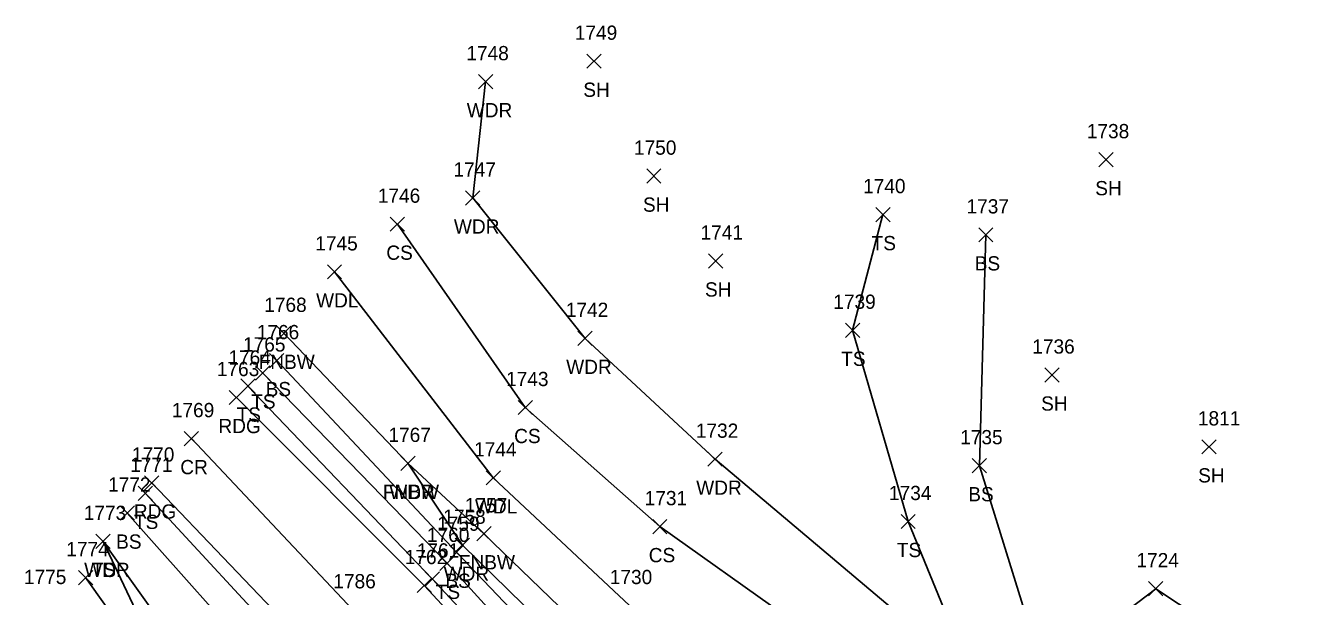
# Model space of a CAD drawing. Extents: x 1469310 to 1475157, y 493997 to 498873.
# Drawn here: x 1469330.9 to 1469508.8, y 498792.5 to 498872.6 of the extents above; entities that cross this region are included whole.
import ezdxf

# ---------------------------------------------------------------- set-up
doc = ezdxf.new("R2010")
doc.units = 0
for name, color, linetype in [('L_A', 7, 'Continuous'), ('L_I', 7, 'Continuous'), ('L_TIC', 7, 'Continuous'), ('LAWA', 7, 'Continuous'), ('LELB', 7, 'Continuous'), ('LFNC', 7, 'Continuous'), ('P_A', 7, 'Continuous'), ('P_I', 7, 'Continuous'), ('P_TIC', 7, 'Continuous'), ('PEU', 7, 'Continuous'), ('PRC', 7, 'Continuous')]:
    doc.layers.add(name, color=color, linetype=linetype)

msp = doc.modelspace()

# ---------------------------------------------------------------- linework, layer by layer
at = {"layer": 'L_TIC'}
for points in [[(1469409.64, 498866.62), (1469411.64, 498868.62)], [(1469411.64, 498866.62), (1469409.64, 498868.62)], [(1469394.42, 498863.75), (1469396.42, 498865.75)], [(1469396.42, 498863.75), (1469394.42, 498865.75)], [(1469481.45, 498852.81), (1469483.45, 498854.81)], [(1469483.45, 498852.81), (1469481.45, 498854.81)], [(1469418.02, 498850.5), (1469420.02, 498852.5)], [(1469420.02, 498850.5), (1469418.02, 498852.5)], [(1469392.62, 498847.43), (1469394.62, 498849.43)], [(1469394.62, 498847.43), (1469392.62, 498849.43)], [(1469450.16, 498845.1), (1469452.16, 498847.1)], [(1469452.16, 498845.1), (1469450.16, 498847.1)], [(1469382.05, 498843.76), (1469384.05, 498845.76)], [(1469384.05, 498843.76), (1469382.05, 498845.76)], [(1469464.59, 498842.26), (1469466.59, 498844.26)], [(1469466.59, 498842.26), (1469464.59, 498844.26)], [(1469373.23, 498837.07), (1469375.23, 498839.07)], [(1469375.23, 498837.07), (1469373.23, 498839.07)], [(1469426.71, 498838.6), (1469428.71, 498840.6)], [(1469428.71, 498838.6), (1469426.71, 498840.6)], [(1469366.12, 498828.45), (1469368.12, 498830.45)], [(1469368.12, 498828.45), (1469366.12, 498830.45)], [(1469445.9, 498828.88), (1469447.9, 498830.88)], [(1469447.9, 498828.88), (1469445.9, 498830.88)], [(1469408.37, 498827.74), (1469410.37, 498829.74)], [(1469410.37, 498827.74), (1469408.37, 498829.74)], [(1469365.13, 498824.62), (1469367.13, 498826.62)], [(1469367.13, 498824.62), (1469365.13, 498826.62)], [(1469363.14, 498822.89), (1469365.14, 498824.89)], [(1469365.14, 498822.89), (1469363.14, 498824.89)], [(1469361.09, 498821.05), (1469363.09, 498823.05)], [(1469363.09, 498821.05), (1469361.09, 498823.05)], [(1469473.86, 498822.6), (1469475.86, 498824.6)], [(1469475.86, 498822.6), (1469473.86, 498824.6)], [(1469399.99, 498818.04), (1469401.99, 498820.04)], [(1469401.99, 498818.04), (1469399.99, 498820.04)], [(1469495.89, 498812.52), (1469497.89, 498814.52)], [(1469497.89, 498812.52), (1469495.89, 498814.52)], [(1469383.54, 498810.21), (1469385.54, 498812.21)], [(1469385.54, 498810.21), (1469383.54, 498812.21)], [(1469383.54, 498810.21), (1469385.54, 498812.21)], [(1469385.54, 498810.21), (1469383.54, 498812.21)], [(1469426.61, 498810.79), (1469428.61, 498812.79)], [(1469428.61, 498810.79), (1469426.61, 498812.79)], [(1469463.69, 498809.88), (1469465.69, 498811.88)], [(1469465.69, 498809.88), (1469463.69, 498811.88)], [(1469395.51, 498808.17), (1469397.51, 498810.17)], [(1469397.51, 498808.17), (1469395.51, 498810.17)], [(1469346.69, 498806), (1469348.69, 498808)], [(1469348.69, 498806), (1469346.69, 498808)], [(1469344.16, 498803.23), (1469346.16, 498805.23)], [(1469346.16, 498803.23), (1469344.16, 498805.23)], [(1469418.87, 498801.33), (1469420.87, 498803.33)], [(1469420.87, 498801.33), (1469418.87, 498803.33)], [(1469453.7, 498802.05), (1469455.7, 498804.05)], [(1469455.7, 498802.05), (1469453.7, 498804.05)], [(1469394.2, 498800.33), (1469396.2, 498802.33)], [(1469396.2, 498800.33), (1469394.2, 498802.33)], [(1469340.76, 498799.26), (1469342.76, 498801.26)], [(1469342.76, 498799.26), (1469340.76, 498801.26)], [(1469340.76, 498799.26), (1469342.76, 498801.26)], [(1469342.76, 498799.26), (1469340.76, 498801.26)], [(1469390.34, 498797.74), (1469392.34, 498799.74)], [(1469392.34, 498797.74), (1469390.34, 498799.74)], [(1469391.18, 498798.73), (1469393.18, 498800.73)], [(1469393.18, 498798.73), (1469391.18, 498800.73)], [(1469389.02, 498796.18), (1469391.02, 498798.18)], [(1469391.02, 498796.18), (1469389.02, 498798.18)], [(1469338.31, 498794.18), (1469340.31, 498796.18)], [(1469340.31, 498794.18), (1469338.31, 498796.18)], [(1469386.95, 498793.99), (1469388.95, 498795.99)], [(1469388.95, 498793.99), (1469386.95, 498795.99)], [(1469488.42, 498792.62), (1469490.42, 498794.62)], [(1469490.42, 498792.62), (1469488.42, 498794.62)]]:
    msp.add_lwpolyline(points, dxfattribs=at)
at = {"layer": 'LAWA'}
for points in [[(1469639.57, 498698.43), (1469608.35, 498698.81), (1469602.51, 498699.12), (1469553.35, 498720.92), (1469557.66, 498736.35), (1469502.31, 498785.09), (1469489.42, 498793.62), (1469479.51, 498786.07), (1469473.54, 498782.36), (1469463.54, 498781.5), (1469427.61, 498811.79), (1469409.37, 498828.74), (1469393.62, 498848.43), (1469395.42, 498864.75)], [(1469550.26, 498635.87), (1469551.34, 498638.82), (1469543.79, 498653.66), (1469517, 498693.69), (1469493.7, 498717.29), (1469464.73, 498743.89), (1469442.45, 498767.36), (1469415.63, 498791.26), (1469396.51, 498809.17), (1469374.23, 498838.07)], [(1469550.26, 498635.87), (1469544.55, 498639.35), (1469529.26, 498656.59), (1469521.27, 498666.89), (1469499.1, 498691), (1469482.91, 498705.54), (1469469.32, 498718.6), (1469451.08, 498739.43), (1469431.27, 498758.58), (1469415.67, 498776.75), (1469392.18, 498799.73), (1469384.54, 498811.21)], [(1469341.76, 498800.26), (1469353.78, 498774.83), (1469366.68, 498750.34), (1469388.97, 498724.88)]]:
    msp.add_lwpolyline(points, dxfattribs=at)
at = {"layer": 'LELB'}
for points in [[(1469609.73, 498671.93), (1469579.3, 498664.24), (1469559.68, 498683.15), (1469537.62, 498706.16), (1469513.73, 498727.48), (1469478.41, 498761.91), (1469463.54, 498781.5), (1469454.7, 498803.05), (1469446.9, 498829.88), (1469451.16, 498846.1)], [(1469689.87, 498657.87), (1469664.2, 498669.39), (1469609.73, 498671.93), (1469582.14, 498658.76), (1469563.4, 498646.02), (1469554.48, 498659.45), (1469546.06, 498676.67), (1469525.38, 498698.23), (1469503.85, 498725.44), (1469472.45, 498754.54), (1469455.13, 498777.29), (1469419.87, 498802.33), (1469400.99, 498819.04), (1469383.05, 498844.76)], [(1469608.35, 498698.81), (1469602.82, 498680.15), (1469584.31, 498668.47), (1469565.41, 498686.22), (1469541.77, 498713.19), (1469523.97, 498731.2), (1469486.88, 498766.71), (1469473.54, 498782.36), (1469464.69, 498810.88), (1469465.59, 498843.26)], [(1469469.32, 498718.6), (1469450.25, 498737.56), (1469430.69, 498757.59), (1469415.11, 498773.82), (1469391.34, 498798.74), (1469366.13, 498825.62)], [(1469596.34, 498559.71), (1469578.35, 498585.4), (1469563.74, 498607.63), (1469555.37, 498620.37), (1469550.82, 498626.65), (1469541.68, 498637.32), (1469517.52, 498662), (1469494.24, 498687.27), (1469477.2, 498705.84), (1469448.36, 498735.3), (1469427.59, 498756.34), (1469413.62, 498771.3), (1469390.02, 498797.18), (1469364.14, 498823.89)], [(1469563.74, 498607.63), (1469555.09, 498616.5), (1469548.65, 498625.25), (1469539.23, 498636.49), (1469516.21, 498660.23), (1469492, 498685.05), (1469474.24, 498704.18), (1469446.06, 498733.49), (1469425.87, 498754.55), (1469411.99, 498769.1), (1469387.95, 498794.99), (1469362.09, 498822.05)], [(1469347.69, 498807), (1469368.78, 498784.2), (1469396.87, 498755.94)], [(1469345.16, 498804.23), (1469365.22, 498781.69), (1469392.79, 498752.52)], [(1469341.76, 498800.26), (1469358.07, 498777.47), (1469371.22, 498753.86)], [(1469339.31, 498795.18), (1469353.78, 498774.83), (1469371.22, 498753.86)]]:
    msp.add_lwpolyline(points, dxfattribs=at)
at = {"layer": 'LFNC'}
msp.add_lwpolyline([(1469557.57, 498626.92), (1469550.26, 498635.87), (1469522.29, 498667.62), (1469500.25, 498692.91), (1469472.78, 498720.33), (1469454.31, 498738.91), (1469435.59, 498759.19), (1469416.3, 498780.92), (1469395.2, 498801.33), (1469384.54, 498811.21), (1469367.12, 498829.45)], dxfattribs=at)
at = {"layer": 'P_TIC'}
for points in [[(1469359.47, 498819.44), (1469361.47, 498821.44)], [(1469361.47, 498819.44), (1469359.47, 498821.44)], [(1469353.16, 498813.68), (1469355.16, 498815.68)], [(1469355.16, 498813.68), (1469353.16, 498815.68)], [(1469347.6, 498807.45), (1469349.6, 498809.45)], [(1469349.6, 498807.45), (1469347.6, 498809.45)], [(1469385.83, 498793.07), (1469387.83, 498795.07)], [(1469387.83, 498793.07), (1469385.83, 498795.07)]]:
    msp.add_lwpolyline(points, dxfattribs=at)
at = {"layer": 'PEU'}
for points in [[(1469787.29, 498391.19), (1469770.79, 498403.19), (1469744.94, 498420.51), (1469711.23, 498443.77), (1469680.07, 498463.21), (1469651.58, 498483.41), (1469630.63, 498501.52), (1469612.52, 498523.24), (1469599.41, 498542.19), (1469591.57, 498556.6), (1469575.61, 498583.06), (1469557.31, 498607.49), (1469540.09, 498628.65), (1469536.24, 498634.99), (1469514.98, 498658.51), (1469490.83, 498684.27), (1469472.69, 498702.57), (1469444.89, 498732.16), (1469424.97, 498753.74), (1469411.28, 498767.74), (1469386.83, 498794.07), (1469360.47, 498820.44)], [(1469348.6, 498808.45), (1469370.59, 498785.46), (1469397.76, 498757.22)]]:
    msp.add_lwpolyline(points, dxfattribs=at)
at = {"layer": 'PRC'}
msp.add_lwpolyline([(1469354.16, 498814.68), (1469376.82, 498790.67), (1469402.92, 498764.19)], dxfattribs=at)

# ---------------------------------------------------------------- texts
at = {"layer": 'L_A'}
for s, p in [('SH', (1469409.13, 498862.62)), ('WDR', (1469392.78, 498859.75)), ('SH', (1469480.94, 498848.81)), ('SH', (1469417.5, 498846.5)), ('WDR', (1469390.98, 498843.43)), ('TS', (1469449.57, 498841.1)), ('CS', (1469381.5, 498839.76)), ('BS', (1469464.03, 498838.26)), ('SH', (1469426.2, 498834.6)), ('WDL', (1469371.65, 498833.07)), ('FNBW', (1469363.59, 498824.45)), ('TS', (1469445.31, 498824.88)), ('WDR', (1469406.73, 498823.74)), ('BS', (1469364.57, 498820.62)), ('TS', (1469362.55, 498818.89)), ('SH', (1469473.35, 498818.6)), ('TS', (1469360.5, 498817.05)), ('CS', (1469399.43, 498814.04)), ('SH', (1469495.38, 498808.52)), ('WDR', (1469424.97, 498806.79)), ('FNBW', (1469381.02, 498806.21)), ('WDR', (1469381.91, 498806.21)), ('BS', (1469463.13, 498805.88)), ('WDL', (1469393.93, 498804.17)), ('TS', (1469346.1, 498802)), ('BS', (1469343.6, 498799.23)), ('TS', (1469453.11, 498798.05)), ('FNBW', (1469391.67, 498796.33)), ('CS', (1469418.31, 498797.33)), ('WDR', (1469339.12, 498795.26)), ('TS', (1469340.17, 498795.26)), ('WDR', (1469389.54, 498794.73)), ('BS', (1469389.78, 498793.74)), ('TS', (1469388.43, 498792.18))]:
    msp.add_text(s, height=2, dxfattribs=at).set_placement(p)
at = {"layer": 'L_I'}
for s, p in [('1749', (1469407.94, 498870.62)), ('1748', (1469392.73, 498867.75)), ('1738', (1469479.76, 498856.81)), ('1750', (1469416.24, 498854.5)), ('1747', (1469390.92, 498851.43)), ('1746', (1469380.31, 498847.76)), ('1740', (1469448.38, 498849.1)), ('1737', (1469462.89, 498846.26)), ('1741', (1469425.58, 498842.6)), ('1745', (1469371.54, 498841.07)), ('1768', (1469364.38, 498832.45)), ('1742', (1469406.68, 498831.74)), ('1739', (1469444.2, 498832.88)), ('1766', (1469363.33, 498828.62)), ('1765', (1469361.4, 498826.89)), ('1736', (1469472.11, 498826.6)), ('1764', (1469359.35, 498825.05)), ('1743', (1469398.3, 498822.04)), ('1811', (1469495.34, 498816.52)), ('1767', (1469381.8, 498814.21)), ('1767', (1469381.8, 498814.21)), ('1732', (1469424.92, 498814.79)), ('1735', (1469462, 498813.88)), ('1744', (1469393.82, 498812.17)), ('1771', (1469345.57, 498810)), ('1772', (1469342.47, 498807.23)), ('1731', (1469417.74, 498805.33)), ('1734', (1469452.01, 498806.05)), ('1773', (1469339.06, 498803.26)), ('1773', (1469339.06, 498803.26)), ('1757', (1469392.5, 498804.33)), ('1759', (1469388.63, 498801.74)), ('1758', (1469389.49, 498802.73)), ('1760', (1469387.2, 498800.18)), ('1774', (1469336.61, 498798.18)), ('1761', (1469385.77, 498797.99)), ('1724', (1469486.72, 498796.62)), ('1775', (1469330.67, 498794.27)), ('1730', (1469412.85, 498794.26))]:
    msp.add_text(s, height=2, dxfattribs=at).set_placement(p)
at = {"layer": 'P_A'}
for s, p in [('RDG', (1469357.95, 498815.44)), ('CR', (1469352.6, 498809.68)), ('RDG', (1469346.09, 498803.45))]:
    msp.add_text(s, height=2, dxfattribs=at).set_placement(p)
at = {"layer": 'P_I'}
for s, p in [('1763', (1469357.73, 498823.44)), ('1769', (1469351.42, 498817.68)), ('1770', (1469345.82, 498811.45)), ('1762', (1469384.09, 498797.07)), ('1786', (1469374.07, 498793.67))]:
    msp.add_text(s, height=2, dxfattribs=at).set_placement(p)

doc.saveas('drawing.dxf')
